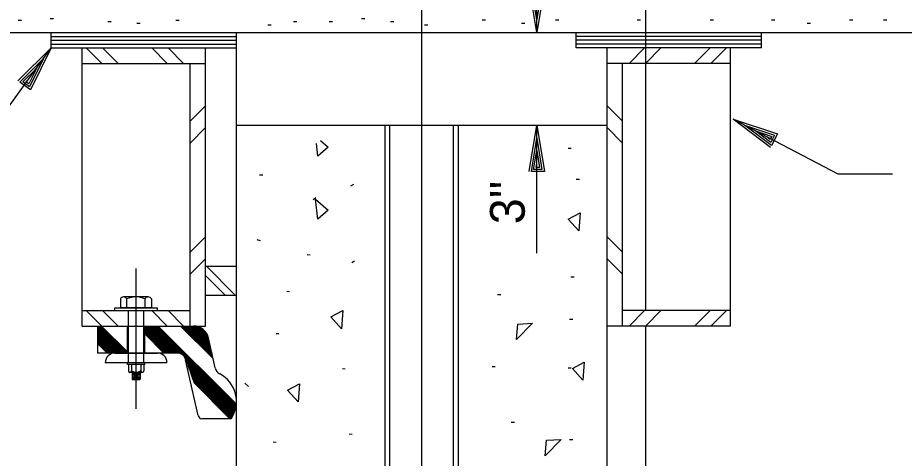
# Model space of a CAD drawing. Extents: x 22388.1 to 22405.7, y 22369.6 to 22390.4.
# Drawn here: x 22402.937 to 22404.133, y 22386.705 to 22387.299 of the extents above; entities that cross this region are included whole.
import ezdxf

# ---------------------------------------------------------------- set-up
doc = ezdxf.new("R2010")
doc.units = 0
for name, color, linetype in [('Level 1', 7, 'Continuous'), ('Level 2', 7, 'Continuous'), ('Level 44', 7, 'Continuous'), ('Level 50', 7, 'Continuous'), ('Level 7', 7, 'Continuous')]:
    doc.layers.add(name, color=color, linetype=linetype)

msp = doc.modelspace()

# ---------------------------------------------------------------- linework, layer by layer
at = {"layer": 'Level 1'}
for p, q in [((22403.482, 22383.7104), (22403.482, 22390.1172)), ((22403.6372, 22387.2793), (22403.6372, 22387.4238)), ((22402.982, 22387.2741), (22403.232, 22387.2741)), ((22402.982, 22387.2689), (22403.232, 22387.2689)), ((22403.9403, 22387.2741), (22403.6903, 22387.2741)), ((22403.9403, 22387.2689), (22403.6903, 22387.2689)), ((22402.982, 22387.2637), (22403.232, 22387.2637)), ((22403.0501, 22387.2377), (22403.0293, 22387.2585)), ((22403.0722, 22387.2377), (22403.0514, 22387.2585)), ((22403.1385, 22387.2377), (22403.1177, 22387.2585)), ((22403.1605, 22387.2377), (22403.1397, 22387.2585)), ((22403.9403, 22387.2637), (22403.6903, 22387.2637)), ((22403.732, 22386.8835), (22403.732, 22387.2585)), ((22403.7617, 22387.2377), (22403.7825, 22387.2585)), ((22403.7838, 22387.2377), (22403.8046, 22387.2585)), ((22403.8501, 22387.2377), (22403.8709, 22387.2585)), ((22403.8722, 22387.2377), (22403.893, 22387.2585)), ((22403.1695, 22387.1597), (22403.1903, 22387.1805)), ((22403.7528, 22387.1597), (22403.732, 22387.1805)), ((22403.1695, 22387.1302), (22403.1903, 22387.1511)), ((22403.6372, 22386.9818), (22403.6372, 22387.1543)), ((22403.7528, 22387.1302), (22403.732, 22387.1511)), ((22403.1695, 22386.9829), (22403.1903, 22387.0037)), ((22403.7528, 22386.9829), (22403.732, 22387.0037)), ((22403.1695, 22386.9535), (22403.1903, 22386.9743)), ((22403.7528, 22386.9535), (22403.732, 22386.9743)), ((22403.0965, 22386.7716), (22403.0965, 22386.9611)), ((22403.2294, 22386.9262), (22403.1914, 22386.9642)), ((22403.2168, 22386.9252), (22403.1903, 22386.9517)), ((22403.1128, 22386.9228), (22403.0796, 22386.9228)), ((22403.0754, 22386.92), (22403.0754, 22386.9082)), ((22403.0838, 22386.92), (22403.0838, 22386.9082)), ((22403.1085, 22386.9201), (22403.1085, 22386.9082)), ((22403.1171, 22386.92), (22403.1171, 22386.9082)), ((22403.0501, 22386.8835), (22403.0293, 22386.9043)), ((22403.0722, 22386.8835), (22403.0514, 22386.9043)), ((22403.0679, 22386.9082), (22403.1252, 22386.9082)), ((22403.0679, 22386.9043), (22403.0679, 22386.9082)), ((22403.1171, 22386.9082), (22403.0754, 22386.9082)), ((22403.0861, 22386.834), (22403.0861, 22386.9043)), ((22403.107, 22386.834), (22403.107, 22386.9043)), ((22403.1385, 22386.8835), (22403.1176, 22386.9043)), ((22403.1252, 22386.9043), (22403.1252, 22386.9082)), ((22403.1606, 22386.8835), (22403.1397, 22386.9043)), ((22403.7617, 22386.8835), (22403.7825, 22386.9043)), ((22403.7838, 22386.8835), (22403.8046, 22386.9043)), ((22403.8501, 22386.8835), (22403.8709, 22386.9043)), ((22403.8722, 22386.8835), (22403.893, 22386.9043)), ((22403.0848, 22386.8314), (22403.0848, 22386.834)), ((22403.1083, 22386.8314), (22403.0848, 22386.8314)), ((22403.0861, 22386.8314), (22403.0861, 22386.8231)), ((22403.0903, 22386.8314), (22403.0903, 22386.8231)), ((22403.1027, 22386.8314), (22403.1027, 22386.8231)), ((22403.107, 22386.8314), (22403.107, 22386.8231)), ((22403.1083, 22386.8314), (22403.1083, 22386.834)), ((22403.0861, 22386.8231), (22403.0861, 22386.8231)), ((22403.1048, 22386.821), (22403.0882, 22386.821)), ((22403.0913, 22386.821), (22403.0913, 22386.8117)), ((22403.1018, 22386.8199), (22403.0913, 22386.8199)), ((22403.1018, 22386.8179), (22403.0913, 22386.8179)), ((22403.1018, 22386.8158), (22403.0913, 22386.8158)), ((22403.1018, 22386.8137), (22403.0913, 22386.8137)), ((22403.0991, 22386.8189), (22403.0937, 22386.8189)), ((22403.0991, 22386.8168), (22403.0937, 22386.8168)), ((22403.0991, 22386.8147), (22403.0937, 22386.8147)), ((22403.1018, 22386.821), (22403.1018, 22386.8116)), ((22403.0913, 22386.8117), (22403.0919, 22386.8111)), ((22403.1018, 22386.8116), (22403.0913, 22386.8116)), ((22403.1012, 22386.8111), (22403.0919, 22386.8111)), ((22403.0991, 22386.8126), (22403.0937, 22386.8126)), ((22403.1018, 22386.8116), (22403.1012, 22386.8111))]:
    msp.add_line(p, q, dxfattribs=at)
for centre, radius, start, end in [((22403.0796, 22386.9182), 0.00456, 22.375, 157.1995), ((22403.0962, 22386.8943), 0.0285, 64.5519, 115.884), ((22403.1128, 22386.9181), 0.00469, 23.1675, 155.9991), ((22403.0882, 22386.8231), 0.00211, 180.4975, 359.5025), ((22403.0965, 22386.8311), 0.0101, 232.4343, 307.5657), ((22403.1049, 22386.8231), 0.00211, 180.5659, 359.4341)]:
    msp.add_arc(centre, radius, start, end, dxfattribs=at)
at = {"layer": 'Level 2'}
for p, q in [((22403.6372, 22387.2967), (22403.6372, 22387.2967)), ((22402.5549, 22387.2793), (22404.3097, 22387.2793)), ((22402.982, 22387.2585), (22402.982, 22387.2793)), ((22403.232, 22386.9252), (22403.232, 22387.2793)), ((22403.6372, 22387.2793), (22403.6372, 22387.2793)), ((22403.6903, 22387.2585), (22403.6903, 22387.2793)), ((22403.9403, 22387.2585), (22403.9403, 22387.2793)), ((22402.982, 22387.2585), (22403.232, 22387.2585)), ((22402.982, 22387.2585), (22402.982, 22387.2585)), ((22403.0236, 22386.8835), (22403.0236, 22387.2585)), ((22403.1903, 22386.8835), (22403.1903, 22387.2585)), ((22403.9403, 22387.2585), (22403.6903, 22387.2585)), ((22403.8986, 22386.8835), (22403.8986, 22387.2585)), ((22402.9718, 22387.2444), (22402.9718, 22387.2444)), ((22403.0236, 22387.2377), (22403.1903, 22387.2377)), ((22403.1695, 22386.8835), (22403.1695, 22387.2377)), ((22403.8986, 22387.2377), (22403.732, 22387.2377)), ((22403.7528, 22386.8835), (22403.7528, 22387.2377)), ((22403.902, 22387.1625), (22403.902, 22387.1625)), ((22403.4325, 22385.8146), (22403.4325, 22387.1543)), ((22403.4389, 22385.7644), (22403.4389, 22387.1543)), ((22403.525, 22385.7712), (22403.525, 22387.1543)), ((22403.5314, 22385.8146), (22403.5314, 22387.1543)), ((22403.6372, 22387.1543), (22403.6372, 22387.1543)), ((22403.9174, 22387.1544), (22403.9174, 22387.1544)), ((22403.6372, 22387.137), (22403.6372, 22387.137)), ((22403.1903, 22386.9642), (22403.232, 22386.9642)), ((22403.1903, 22386.9252), (22403.232, 22386.9252)), ((22403.0236, 22386.9043), (22403.1695, 22386.9043)), ((22403.8986, 22386.9043), (22403.7528, 22386.9043)), ((22403.0236, 22386.8835), (22403.1903, 22386.8835)), ((22403.0445, 22386.8835), (22403.0445, 22386.847)), ((22403.0445, 22386.8835), (22403.1739, 22386.8835)), ((22403.0848, 22386.847), (22403.0848, 22386.8835)), ((22403.1083, 22386.847), (22403.1083, 22386.8835)), ((22403.8986, 22386.8835), (22403.732, 22386.8835)), ((22403.2032, 22386.8269), (22403.1942, 22386.8672)), ((22403.152, 22386.847), (22403.0445, 22386.847)), ((22403.0679, 22386.847), (22403.1252, 22386.847)), ((22403.1803, 22386.7626), (22403.1634, 22386.8379)), ((22403.1382, 22386.834), (22403.0549, 22386.834)), ((22403.2247, 22386.7585), (22403.1854, 22386.7585))]:
    msp.add_line(p, q, dxfattribs=at)
for points in [[(22403.6476, 22387.3417), (22403.6372, 22387.2793), (22403.6269, 22387.3417), (22403.6446, 22387.3417), (22403.6372, 22387.2967), (22403.6302, 22387.339), (22403.6416, 22387.339), (22403.6372, 22387.3133), (22403.6336, 22387.3363), (22403.6382, 22387.3363), (22403.6372, 22387.3307)], [(22402.7608, 22387.0386), (22402.8232, 22387.0386), (22402.982, 22387.2585)], [(22402.9371, 22387.214), (22402.982, 22387.2585), (22402.9539, 22387.2019), (22402.9395, 22387.2122), (22402.9718, 22387.2444), (22402.9527, 22387.206), (22402.9435, 22387.2127), (22402.9621, 22387.2309), (22402.9516, 22387.2101), (22402.9478, 22387.2129), (22402.9519, 22387.2169)], [(22404.1173, 22387.0881), (22404.0436, 22387.0881), (22403.902, 22387.1625)], [(22403.9524, 22387.1243), (22403.902, 22387.1625), (22403.962, 22387.1426), (22403.9538, 22387.127), (22403.9174, 22387.1544), (22403.9581, 22387.1409), (22403.9528, 22387.1309), (22403.9321, 22387.1467), (22403.9542, 22387.1392), (22403.952, 22387.1351), (22403.9475, 22387.1386)], [(22403.6269, 22387.092), (22403.6372, 22387.1543), (22403.6476, 22387.092), (22403.6299, 22387.092), (22403.6372, 22387.137), (22403.6442, 22387.0947), (22403.6329, 22387.0947), (22403.6372, 22387.1203), (22403.6409, 22387.0973), (22403.6362, 22387.0973), (22403.6372, 22387.103)]]:
    msp.add_lwpolyline(points, dxfattribs=at)
for centre, radius, start, end in [((22403.1739, 22386.8627), 0.0208, 12.6173, 90), ((22403.0679, 22386.834), 0.013, 90, 180), ((22403.1252, 22386.834), 0.013, 0, 90), ((22403.152, 22386.8353), 0.0117, 12.6194, 90), ((22403.2147, 22386.8294), 0.0117, 192.6165, 242.8295), ((22403.1903, 22386.7819), 0.0417, 325.7711, 62.8295), ((22403.1854, 22386.7637), 0.00521, 192.6179, 270)]:
    msp.add_arc(centre, radius, start, end, dxfattribs=at)
at = {"layer": 'Level 44'}
for p, q in [((22402.9372, 22387.2961), (22402.9417, 22387.2961)), ((22402.9805, 22387.2983), (22402.985, 22387.2983)), ((22403.0585, 22387.294), (22403.063, 22387.294)), ((22403.1503, 22387.2961), (22403.1548, 22387.2961)), ((22403.3089, 22387.294), (22403.3134, 22387.294)), ((22403.3571, 22387.294), (22403.3616, 22387.294)), ((22403.4007, 22387.2983), (22403.4052, 22387.2983)), ((22403.4397, 22387.294), (22403.4442, 22387.294)), ((22403.5636, 22387.2962), (22403.5681, 22387.2962)), ((22403.6623, 22387.2962), (22403.6668, 22387.2962)), ((22403.7724, 22387.2962), (22403.7769, 22387.2962)), ((22403.8711, 22387.2962), (22403.8756, 22387.2962)), ((22403.9537, 22387.2962), (22403.9582, 22387.2962)), ((22404.0592, 22387.2962), (22404.0637, 22387.2962)), ((22404.1051, 22387.2962), (22404.1096, 22387.2962)), ((22403.0975, 22387.2918), (22403.102, 22387.2918)), ((22403.2745, 22387.2897), (22403.279, 22387.2897)), ((22403.4856, 22387.2897), (22403.4901, 22387.2897)), ((22403.6164, 22387.2919), (22403.6209, 22387.2919)), ((22404.0019, 22387.2919), (22404.0064, 22387.2919)), ((22403.6795, 22387.1235), (22403.6837, 22387.1235)), ((22403.263, 22387.0874), (22403.2675, 22387.0874)), ((22403.6905, 22387.0814), (22403.6947, 22387.0814)), ((22403.3863, 22387.0724), (22403.3901, 22387.0746)), ((22403.3353, 22387.0543), (22403.339, 22387.0566)), ((22403.2595, 22387.0002), (22403.264, 22386.9989)), ((22403.3275, 22386.9798), (22403.3312, 22386.9794)), ((22403.3874, 22386.9693), (22403.3911, 22386.9716)), ((22403.6831, 22386.9496), (22403.6874, 22386.9496)), ((22403.3, 22386.9303), (22403.3037, 22386.93)), ((22403.5843, 22386.9258), (22403.5886, 22386.9258)), ((22403.6813, 22386.8928), (22403.6856, 22386.8928)), ((22403.0806, 22386.847), (22403.0445, 22386.8832)), ((22403.0799, 22386.847), (22403.0445, 22386.8825)), ((22403.0792, 22386.847), (22403.0445, 22386.8818)), ((22403.0785, 22386.847), (22403.0445, 22386.881)), ((22403.0778, 22386.847), (22403.0445, 22386.8803)), ((22403.0771, 22386.847), (22403.0445, 22386.8796)), ((22403.0764, 22386.847), (22403.0445, 22386.8789)), ((22403.0757, 22386.847), (22403.0445, 22386.8782)), ((22403.0749, 22386.847), (22403.0445, 22386.8775)), ((22403.0742, 22386.847), (22403.0445, 22386.8768)), ((22403.0735, 22386.847), (22403.0445, 22386.8761)), ((22403.0728, 22386.847), (22403.0445, 22386.8754)), ((22403.0721, 22386.847), (22403.0445, 22386.8747)), ((22403.0714, 22386.847), (22403.0445, 22386.874)), ((22403.0813, 22386.847), (22403.0448, 22386.8835)), ((22403.082, 22386.847), (22403.0456, 22386.8835)), ((22403.0827, 22386.847), (22403.0463, 22386.8835)), ((22403.0834, 22386.847), (22403.047, 22386.8835)), ((22403.0841, 22386.847), (22403.0477, 22386.8835)), ((22403.0848, 22386.847), (22403.0484, 22386.8835)), ((22403.0848, 22386.8478), (22403.0491, 22386.8835)), ((22403.0848, 22386.8485), (22403.0498, 22386.8835)), ((22403.0848, 22386.8485), (22403.0498, 22386.8835)), ((22403.1446, 22386.847), (22403.1082, 22386.8835)), ((22403.1439, 22386.847), (22403.1083, 22386.8827)), ((22403.1432, 22386.847), (22403.1083, 22386.882)), ((22403.1425, 22386.847), (22403.1083, 22386.8813)), ((22403.1418, 22386.847), (22403.1083, 22386.8806)), ((22403.1411, 22386.847), (22403.1083, 22386.8799)), ((22403.1404, 22386.847), (22403.1083, 22386.8791)), ((22403.1397, 22386.847), (22403.1083, 22386.8784)), ((22403.139, 22386.847), (22403.1083, 22386.8777)), ((22403.1382, 22386.847), (22403.1083, 22386.877)), ((22403.1375, 22386.847), (22403.1083, 22386.8763)), ((22403.1368, 22386.847), (22403.1083, 22386.8756)), ((22403.1361, 22386.847), (22403.1083, 22386.8749)), ((22403.1354, 22386.847), (22403.1083, 22386.8742)), ((22403.1347, 22386.847), (22403.1083, 22386.8735)), ((22403.1453, 22386.847), (22403.1089, 22386.8835)), ((22403.146, 22386.847), (22403.1096, 22386.8835)), ((22403.1467, 22386.847), (22403.1103, 22386.8835)), ((22403.1474, 22386.847), (22403.111, 22386.8835)), ((22403.1482, 22386.847), (22403.1117, 22386.8835)), ((22403.1489, 22386.847), (22403.1124, 22386.8835)), ((22403.1496, 22386.847), (22403.1131, 22386.8835)), ((22403.1503, 22386.847), (22403.1138, 22386.8835)), ((22403.151, 22386.847), (22403.1145, 22386.8835)), ((22403.1517, 22386.847), (22403.1152, 22386.8835)), ((22403.1524, 22386.847), (22403.1159, 22386.8835)), ((22403.1531, 22386.847), (22403.1166, 22386.8835)), ((22403.1538, 22386.847), (22403.1174, 22386.8835)), ((22403.1549, 22386.8467), (22403.1181, 22386.8835)), ((22403.1559, 22386.8464), (22403.1188, 22386.8835)), ((22403.157, 22386.8459), (22403.1195, 22386.8835)), ((22403.1587, 22386.845), (22403.1202, 22386.8835)), ((22403.2311, 22386.7733), (22403.1209, 22386.8835)), ((22403.2312, 22386.7739), (22403.1216, 22386.8835)), ((22403.2313, 22386.7745), (22403.1223, 22386.8835)), ((22403.2314, 22386.7751), (22403.123, 22386.8835)), ((22403.2315, 22386.7757), (22403.1237, 22386.8835)), ((22403.2316, 22386.7763), (22403.1244, 22386.8835)), ((22403.2317, 22386.777), (22403.1251, 22386.8835)), ((22403.2317, 22386.7776), (22403.1258, 22386.8835)), ((22403.2318, 22386.7782), (22403.1265, 22386.8835)), ((22403.1565, 22386.8835), (22403.2004, 22386.8396)), ((22403.1572, 22386.8835), (22403.2002, 22386.8404)), ((22403.1579, 22386.8835), (22403.2, 22386.8414)), ((22403.1586, 22386.8835), (22403.1998, 22386.8423)), ((22403.1593, 22386.8835), (22403.1996, 22386.8432)), ((22403.16, 22386.8835), (22403.1994, 22386.8441)), ((22403.1607, 22386.8835), (22403.1992, 22386.845)), ((22403.1614, 22386.8835), (22403.199, 22386.8459)), ((22403.1621, 22386.8835), (22403.1988, 22386.8468)), ((22403.1628, 22386.8835), (22403.1986, 22386.8477)), ((22403.1635, 22386.8835), (22403.1984, 22386.8486)), ((22403.1642, 22386.8835), (22403.1982, 22386.8496)), ((22403.1649, 22386.8835), (22403.1977, 22386.8507)), ((22403.1656, 22386.8835), (22403.1977, 22386.8514)), ((22403.1664, 22386.8835), (22403.1975, 22386.8523)), ((22403.1671, 22386.8835), (22403.1973, 22386.8532)), ((22403.1678, 22386.8835), (22403.1971, 22386.8541)), ((22403.1685, 22386.8835), (22403.1969, 22386.855)), ((22403.1692, 22386.8835), (22403.1967, 22386.8559)), ((22403.1965, 22386.8569), (22403.1699, 22386.8835)), ((22403.1963, 22386.8578), (22403.1706, 22386.8835)), ((22403.1961, 22386.8587), (22403.1713, 22386.8835)), ((22403.1959, 22386.8596), (22403.172, 22386.8835)), ((22403.1957, 22386.8605), (22403.1727, 22386.8835)), ((22403.1955, 22386.8614), (22403.1735, 22386.8834)), ((22403.1953, 22386.8623), (22403.1741, 22386.8835)), ((22403.1951, 22386.8632), (22403.1749, 22386.8835)), ((22403.1949, 22386.8641), (22403.1756, 22386.8834)), ((22403.1947, 22386.8651), (22403.1764, 22386.8833)), ((22403.1945, 22386.866), (22403.1772, 22386.8832)), ((22403.1943, 22386.8669), (22403.1781, 22386.8831)), ((22403.1941, 22386.8678), (22403.179, 22386.8828)), ((22403.1938, 22386.8688), (22403.18, 22386.8826)), ((22403.1934, 22386.8698), (22403.1811, 22386.8822)), ((22403.1928, 22386.8714), (22403.1826, 22386.8816)), ((22403.1917, 22386.8734), (22403.1846, 22386.8805)), ((22403.2854, 22386.8736), (22403.2891, 22386.8732)), ((22403.0707, 22386.847), (22403.0445, 22386.8733)), ((22403.07, 22386.847), (22403.0445, 22386.8726)), ((22403.0693, 22386.847), (22403.0445, 22386.8719)), ((22403.0686, 22386.847), (22403.0445, 22386.8712)), ((22403.0679, 22386.847), (22403.0445, 22386.8704)), ((22403.0672, 22386.847), (22403.0445, 22386.8697)), ((22403.0665, 22386.847), (22403.0445, 22386.869)), ((22403.0658, 22386.847), (22403.0445, 22386.8683)), ((22403.065, 22386.847), (22403.0445, 22386.8676)), ((22403.0643, 22386.847), (22403.0445, 22386.8669)), ((22403.0636, 22386.847), (22403.0445, 22386.8662)), ((22403.0629, 22386.847), (22403.0445, 22386.8655)), ((22403.0622, 22386.847), (22403.0445, 22386.8648)), ((22403.0615, 22386.847), (22403.0445, 22386.8641)), ((22403.0608, 22386.847), (22403.0445, 22386.8634)), ((22403.0601, 22386.847), (22403.0445, 22386.8627)), ((22403.0594, 22386.847), (22403.0445, 22386.862)), ((22403.134, 22386.847), (22403.1083, 22386.8728)), ((22403.0587, 22386.847), (22403.0445, 22386.8613)), ((22403.058, 22386.847), (22403.0445, 22386.8605)), ((22403.0573, 22386.847), (22403.0445, 22386.8598)), ((22403.2309, 22386.7727), (22403.1617, 22386.842)), ((22403.2308, 22386.772), (22403.1629, 22386.8399)), ((22403.2306, 22386.7713), (22403.1634, 22386.8385)), ((22403.2304, 22386.7705), (22403.1639, 22386.837)), ((22403.2302, 22386.7698), (22403.1644, 22386.8356)), ((22403.2299, 22386.7691), (22403.1649, 22386.8342)), ((22403.2297, 22386.7684), (22403.1654, 22386.8328)), ((22403.2295, 22386.7678), (22403.1659, 22386.8313)), ((22403.2292, 22386.7671), (22403.1664, 22386.8299)), ((22403.229, 22386.7664), (22403.1669, 22386.8285)), ((22403.2287, 22386.7658), (22403.1674, 22386.8271)), ((22403.2284, 22386.7651), (22403.1679, 22386.8256)), ((22403.3751, 22386.826), (22403.3787, 22386.8256)), ((22403.577, 22386.8287), (22403.5812, 22386.8287)), ((22403.6795, 22386.8269), (22403.6837, 22386.8269)), ((22403.2281, 22386.7645), (22403.1684, 22386.8242)), ((22403.2278, 22386.7639), (22403.1689, 22386.8228)), ((22403.2275, 22386.7632), (22403.1694, 22386.8214)), ((22403.2272, 22386.7626), (22403.1699, 22386.8199)), ((22403.2269, 22386.762), (22403.1704, 22386.8185)), ((22403.2266, 22386.7614), (22403.1709, 22386.8171)), ((22403.2262, 22386.7609), (22403.1714, 22386.8157)), ((22403.2259, 22386.7603), (22403.1719, 22386.8143)), ((22403.2255, 22386.7597), (22403.1724, 22386.8128)), ((22403.2252, 22386.7592), (22403.1729, 22386.8114)), ((22403.2248, 22386.7586), (22403.1734, 22386.81)), ((22403.224, 22386.7585), (22403.1739, 22386.8086)), ((22403.2231, 22386.7585), (22403.1744, 22386.8072)), ((22403.6026, 22386.7537), (22403.6069, 22386.7537)), ((22403.3842, 22386.7381), (22403.3879, 22386.7377)), ((22403.6813, 22386.7305), (22403.6856, 22386.7305)), ((22403.2817, 22386.7271), (22403.2854, 22386.7267))]:
    msp.add_line(p, q, dxfattribs=at)
for points in [[(22403.3455, 22387.1336), (22403.3559, 22387.1245), (22403.3417, 22387.1126), (22403.3398, 22387.1298)], [(22403.248, 22386.8018), (22403.2432, 22386.8063)]]:
    msp.add_lwpolyline(points, dxfattribs=at)
for points in [[(22403.3388, 22387.0544), (22403.3559, 22387.0395), (22403.3417, 22387.0276)], [(22403.694, 22387.0118), (22403.6797, 22387.0278), (22403.6956, 22387.0363)], [(22403.3737, 22386.8799), (22403.3595, 22386.8959), (22403.3754, 22386.9044)], [(22403.6116, 22386.8862), (22403.6316, 22386.8873), (22403.61, 22386.8652)], [(22403.6994, 22386.8104), (22403.6852, 22386.8264), (22403.7011, 22386.8349)], [(22403.3152, 22386.7811), (22403.3009, 22386.7971), (22403.3168, 22386.8056)], [(22403.6501, 22386.7294), (22403.6701, 22386.7305), (22403.6484, 22386.7084)]]:
    msp.add_lwpolyline(points, close=True, dxfattribs=at)
at = {"layer": 'Level 7'}
for p, q in [((22403.7841, 22386.9043), (22403.7841, 22389.4272)), ((22403.232, 22386.1111), (22403.232, 22387.2585)), ((22403.732, 22386.1111), (22403.732, 22387.2585)), ((22403.232, 22387.1543), (22403.732, 22387.1543)), ((22403.7841, 22386.2882), (22403.7841, 22386.8835))]:
    msp.add_line(p, q, dxfattribs=at)

# ---------------------------------------------------------------- texts
at = {"layer": 'Level 50'}
msp.add_text("3''", height=0.04688, rotation=90, dxfattribs=at).set_placement((22403.6209, 22387.0208))

doc.saveas('drawing.dxf')
